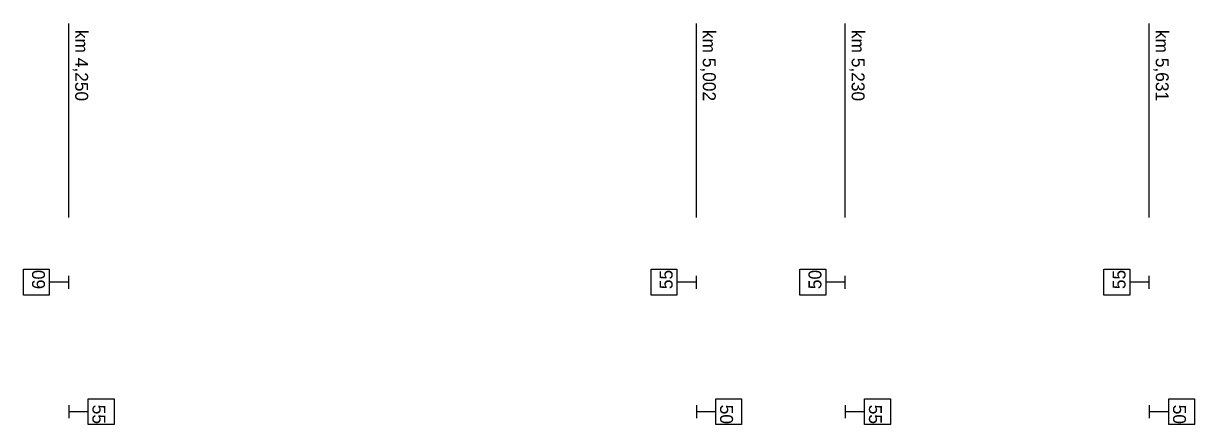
# Model space of a CAD drawing. Extents: x -1424 to 5155, y -2900 to 2050.
# Drawn here: x 2343 to 2524, y 1988 to 2050 of the extents above; entities that cross this region are included whole.
import ezdxf

# ---------------------------------------------------------------- set-up
doc = ezdxf.new("R2010")
doc.units = 0
doc.layers.add('rychlostník', color=7, linetype='Continuous')

msp = doc.modelspace()

# ---------------------------------------------------------------- linework, layer by layer
at = {"layer": 'rychlostník'}
for p, q in [((2350, 2020), (2350, 2050)), ((2447, 2020), (2447, 2050)), ((2447, 2020), (2447, 2050)), ((2470, 2020), (2470, 2050)), ((2470, 2020), (2470, 2050)), ((2517, 2020), (2517, 2050)), ((2517, 2020), (2517, 2050)), ((2343, 2008), (2343, 2012)), ((2343, 2012), (2347, 2012)), ((2347, 2012), (2347, 2008)), ((2350, 2009), (2350, 2011)), ((2440, 2008), (2440, 2012)), ((2440, 2012), (2444, 2012)), ((2444, 2012), (2444, 2008)), ((2447, 2009), (2447, 2011)), ((2463, 2008), (2463, 2012)), ((2463, 2012), (2467, 2012)), ((2467, 2012), (2467, 2008)), ((2470, 2009), (2470, 2011)), ((2510, 2008), (2510, 2012)), ((2510, 2012), (2514, 2012)), ((2514, 2012), (2514, 2008)), ((2517, 2009), (2517, 2011)), ((2350, 2010), (2347, 2010)), ((2442.33, 2010.09), (2442.33, 2010.09)), ((2447, 2010), (2444, 2010)), ((2465.33, 2010.09), (2465.33, 2010.09)), ((2470, 2010), (2467, 2010)), ((2512.33, 2010.09), (2512.33, 2010.09)), ((2517, 2010), (2514, 2010)), ((2347, 2008), (2343, 2008)), ((2444, 2008), (2440, 2008)), ((2467, 2008), (2463, 2008)), ((2514, 2008), (2510, 2008)), ((2353, 1992), (2357, 1992)), ((2353, 1988), (2353, 1992)), ((2357, 1992), (2357, 1988)), ((2450, 1992), (2454, 1992)), ((2450, 1988), (2450, 1992)), ((2454, 1992), (2454, 1988)), ((2473, 1992), (2477, 1992)), ((2473, 1988), (2473, 1992)), ((2477, 1992), (2477, 1988)), ((2520, 1992), (2524, 1992)), ((2520, 1988), (2520, 1992)), ((2524, 1992), (2524, 1988)), ((2350, 1991), (2350, 1989)), ((2350, 1990), (2353, 1990)), ((2447, 1991), (2447, 1989)), ((2447, 1990), (2450, 1990)), ((2451.67, 1989.91), (2451.67, 1989.91)), ((2470, 1991), (2470, 1989)), ((2470, 1990), (2473, 1990)), ((2474.67, 1989.91), (2474.67, 1989.91)), ((2517, 1991), (2517, 1989)), ((2517, 1990), (2520, 1990)), ((2521.67, 1989.91), (2521.67, 1989.91)), ((2357, 1988), (2353, 1988)), ((2454, 1988), (2450, 1988)), ((2477, 1988), (2473, 1988)), ((2524, 1988), (2520, 1988))]:
    msp.add_line(p, q, dxfattribs=at)

# ---------------------------------------------------------------- texts
for s, rotation, p in [('km 4,250', 270, (2351, 2049)), ('km 5,002', 270, (2448, 2049)), ('km 5,230', 270, (2471, 2049)), ('km 5,631', 270, (2518, 2049)), ('60', 90, (2346.33, 2008.93)), ('55', 90, (2443.33, 2008.93)), ('50', 90, (2466.33, 2008.93)), ('55', 90, (2513.33, 2008.93)), ('55', 270, (2353.67, 1991.07)), ('50', 270, (2450.67, 1991.07)), ('55', 270, (2473.67, 1991.07)), ('50', 270, (2520.67, 1991.07))]:
    msp.add_text(s, height=2, rotation=rotation, dxfattribs=at).set_placement(p)

doc.saveas('drawing.dxf')
